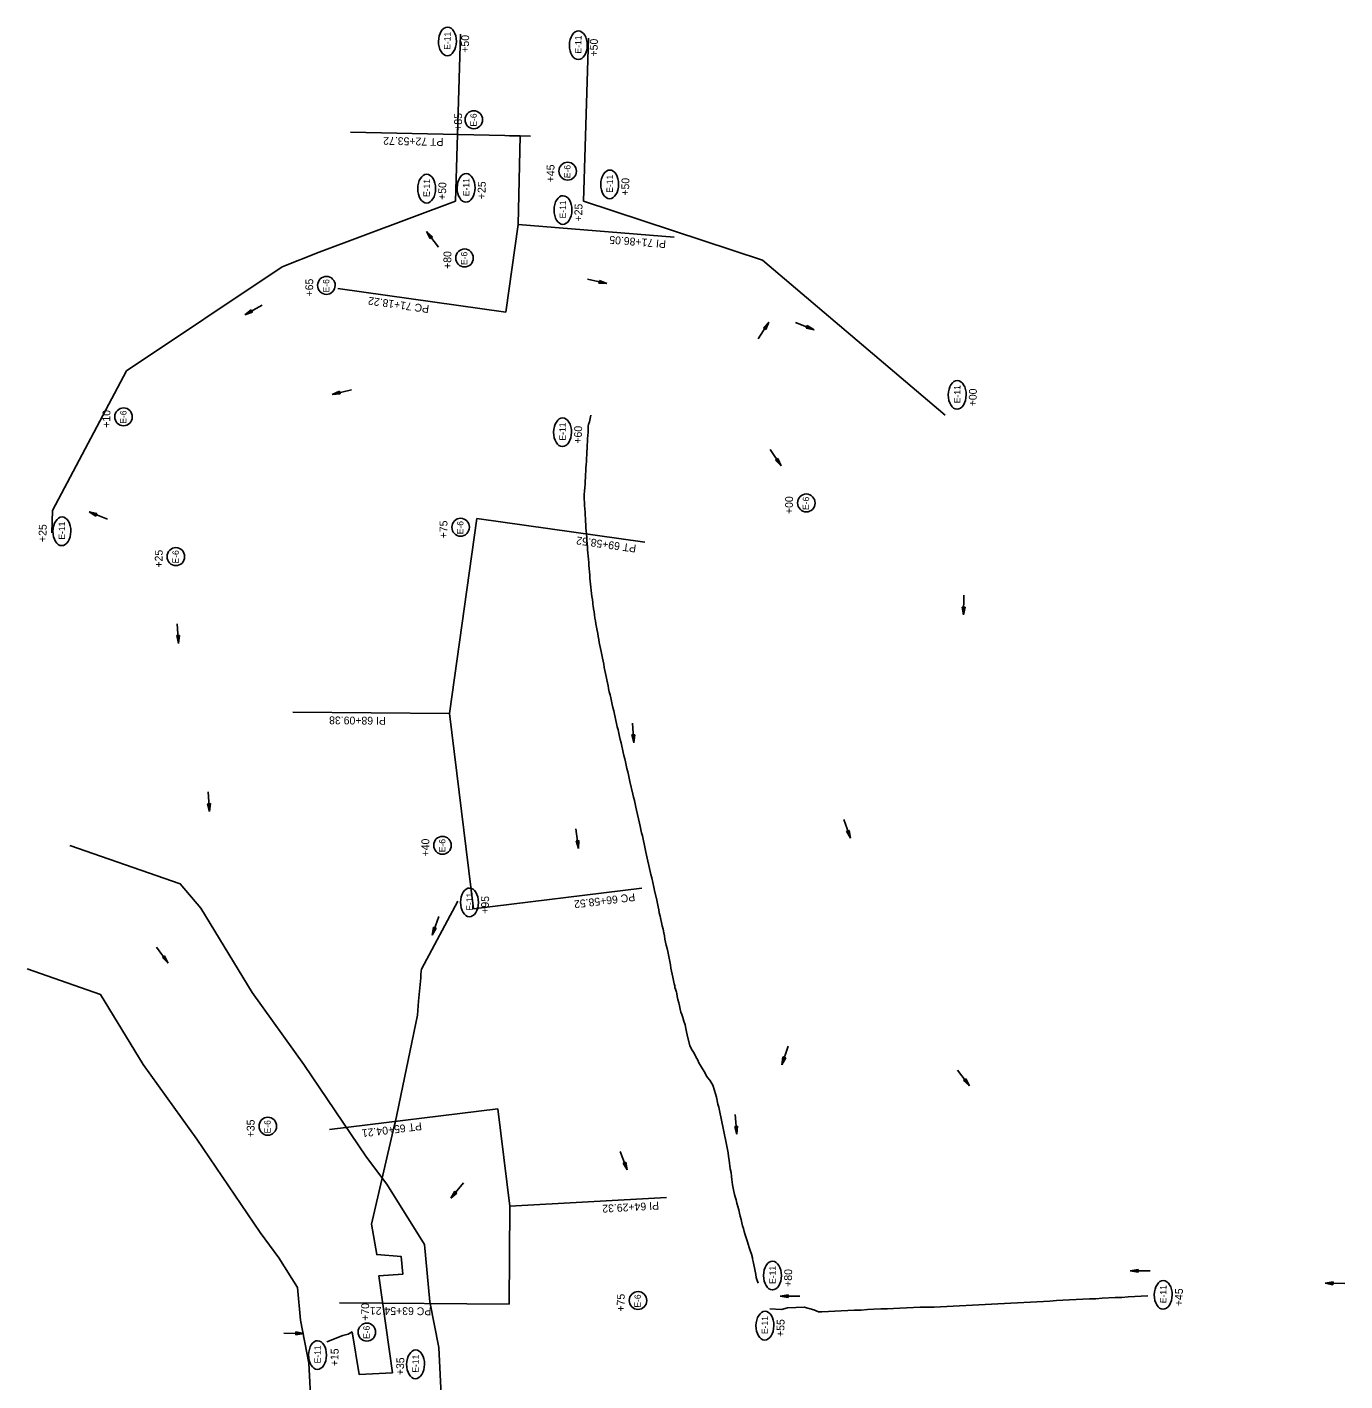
# Model space of a CAD drawing. Extents: x 1312891 to 1314734, y 2088044 to 2090982.
# Drawn here: x 1313631 to 1314640, y 2089414 to 2090451 of the extents above; entities that cross this region are included whole.
import ezdxf

# ---------------------------------------------------------------- set-up
doc = ezdxf.new("R2010")
doc.units = 0
for name, color, linetype in [('43', 7, 'Continuous'), ('44', 7, 'Continuous'), ('Level 1', 7, 'Continuous'), ('Level 44', 7, 'Continuous'), ('R_Buffer', 7, 'Continuous'), ('R_Horz Alg Annot_Detour', 7, 'Continuous'), ('R_Horz Alg Stationing_Detour', 7, 'Continuous')]:
    doc.layers.add(name, color=color, linetype=linetype)

msp = doc.modelspace()

# ---------------------------------------------------------------- linework, layer by layer
at = {"layer": '43'}
for p, q in [((1313936.8, 2090294.8), (1313941.3, 2090290.6)), ((1313939.6, 2090289.3), (1313936.8, 2090294.8)), ((1313941.3, 2090290.6), (1313939.6, 2090289.3)), ((1314068.9, 2090255.1), (1314069.3, 2090257.2)), ((1314075, 2090254.9), (1314068.9, 2090255.1)), ((1314069.3, 2090257.2), (1314075, 2090254.9)), ((1313797.7, 2090230.9), (1313802.5, 2090234.7)), ((1313803.5, 2090232.9), (1313797.7, 2090230.9)), ((1313802.5, 2090234.7), (1313803.5, 2090232.9)), ((1314194.8, 2090220.8), (1314199, 2090225.3)), ((1314199, 2090225.3), (1314196.6, 2090219.6)), ((1314227.6, 2090220.7), (1314228.4, 2090222.7)), ((1314228.4, 2090222.7), (1314233.6, 2090219.4)), ((1314196.6, 2090219.6), (1314194.8, 2090220.8)), ((1314233.6, 2090219.4), (1314227.6, 2090220.7)), ((1313864.5, 2090169.9), (1313870.1, 2090172.4)), ((1313870.1, 2090172.4), (1313870.6, 2090170.3)), ((1313870.6, 2090170.3), (1313864.5, 2090169.9)), ((1314204.1, 2090119.6), (1314205.9, 2090120.8)), ((1314208.4, 2090115.1), (1314204.1, 2090119.6)), ((1314205.9, 2090120.8), (1314208.4, 2090115.1)), ((1313678.3, 2090080), (1313684.3, 2090078.7)), ((1313683.5, 2090076.7), (1313678.3, 2090080)), ((1313684.3, 2090078.7), (1313683.5, 2090076.7)), ((1314348.2, 2090000.9), (1314347.2, 2090007)), ((1314347.2, 2090007), (1314349.4, 2090006.9)), ((1314349.4, 2090006.9), (1314348.2, 2090000.9)), ((1313745.4, 2089985.1), (1313747.5, 2089985.2)), ((1313746.9, 2089979.1), (1313745.4, 2089985.1)), ((1313747.5, 2089985.2), (1313746.9, 2089979.1)), ((1314094.1, 2089909), (1314096.3, 2089909.1)), ((1314095.6, 2089903), (1314094.1, 2089909)), ((1314096.3, 2089909.1), (1314095.6, 2089903)), ((1313769, 2089856.3), (1313771.2, 2089856.4)), ((1313770.5, 2089850.3), (1313769, 2089856.3)), ((1313771.2, 2089856.4), (1313770.5, 2089850.3)), ((1314258.5, 2089835.2), (1314260.5, 2089835.9)), ((1314261.5, 2089829.9), (1314258.5, 2089835.2)), ((1314260.5, 2089835.9), (1314261.5, 2089829.9)), ((1314051.4, 2089827.8), (1314053.5, 2089828.1)), ((1314053.3, 2089821.9), (1314051.4, 2089827.8)), ((1314053.5, 2089828.1), (1314053.3, 2089821.9)), ((1313941, 2089755.6), (1313942.1, 2089761.7)), ((1313944.1, 2089760.9), (1313941, 2089755.6)), ((1313942.1, 2089761.7), (1313944.1, 2089760.9)), ((1313734.5, 2089738.5), (1313736.2, 2089739.7)), ((1313738.9, 2089734.2), (1313734.5, 2089738.5)), ((1313736.2, 2089739.7), (1313738.9, 2089734.2)), ((1314208.9, 2089656.2), (1314209.8, 2089662.3)), ((1314209.8, 2089662.3), (1314211.9, 2089661.6)), ((1314211.9, 2089661.6), (1314208.9, 2089656.2)), ((1314348.2, 2089644.2), (1314349.8, 2089645.6)), ((1314352.7, 2089640.1), (1314348.2, 2089644.2)), ((1314349.8, 2089645.6), (1314352.7, 2089640.1)), ((1314172.9, 2089609), (1314175, 2089609.2)), ((1314174.4, 2089603.1), (1314172.9, 2089609)), ((1314175, 2089609.2), (1314174.4, 2089603.1)), ((1314087.4, 2089581), (1314089.4, 2089581.7)), ((1314090.6, 2089575.7), (1314087.4, 2089581)), ((1314089.4, 2089581.7), (1314090.6, 2089575.7)), ((1313955.4, 2089554), (1313958.4, 2089559.4)), ((1313958.4, 2089559.4), (1313960.1, 2089558)), ((1313960.1, 2089558), (1313955.4, 2089554)), ((1314475.8, 2089498.4), (1314481.9, 2089499.5)), ((1314481.9, 2089497.3), (1314475.8, 2089498.4)), ((1314481.9, 2089499.5), (1314481.9, 2089497.3)), ((1314625.1, 2089488.9), (1314631.2, 2089489.9)), ((1314631.1, 2089487.8), (1314625.1, 2089488.9)), ((1314631.2, 2089489.9), (1314631.1, 2089487.8)), ((1314207.6, 2089479.1), (1314213.7, 2089480.1)), ((1314213.7, 2089478), (1314207.6, 2089479.1)), ((1314213.7, 2089480.1), (1314213.7, 2089478)), ((1313836.6, 2089449.4), (1313836.7, 2089451.6)), ((1313842.7, 2089450.5), (1313836.6, 2089449.4)), ((1313836.7, 2089451.6), (1313842.7, 2089450.5))]:
    msp.add_line(p, q, dxfattribs=at)
for points in [[(1313945.9, 2090282.7), (1313936.8, 2090294.8)], [(1314060.2, 2090258.1), (1314075, 2090254.9)], [(1313811, 2090238.2), (1313797.7, 2090230.9)], [(1314190.8, 2090212.5), (1314199, 2090225.3)], [(1314219.5, 2090225), (1314233.6, 2090219.4)], [(1313879.3, 2090173.4), (1313864.5, 2090169.9)], [(1314199.9, 2090127.7), (1314208.4, 2090115.1)], [(1313692.4, 2090074.3), (1313678.3, 2090080)], [(1314348.4, 2090016.1), (1314348.2, 2090000.9)], [(1313745.8, 2089994.2), (1313746.9, 2089979.1)], [(1314094.6, 2089918.1), (1314095.6, 2089903)], [(1313769.5, 2089865.4), (1313770.5, 2089850.3)], [(1314256.4, 2089844.2), (1314261.5, 2089829.9)], [(1314051.1, 2089837), (1314053.3, 2089821.9)], [(1313946.2, 2089769.9), (1313941, 2089755.6)], [(1313730, 2089746.5), (1313738.9, 2089734.2)], [(1314213.8, 2089670.6), (1314208.9, 2089656.2)], [(1314343.4, 2089652.1), (1314352.7, 2089640.1)], [(1314173.3, 2089618.2), (1314174.4, 2089603.1)], [(1314085.1, 2089589.9), (1314090.6, 2089575.7)], [(1313965, 2089565.8), (1313955.4, 2089554)], [(1314491, 2089498.3), (1314475.8, 2089498.4)], [(1314640.3, 2089488.8), (1314625.1, 2089488.9)], [(1314222.8, 2089479), (1314207.6, 2089479.1)], [(1313827.5, 2089450.6), (1313842.7, 2089450.5)]]:
    msp.add_lwpolyline(points, dxfattribs=at)
at = {"layer": 'Level 1'}
for centre, major_axis, ratio in [((1313952.8, 2090440.3), (0.1, 11), 0.622952), ((1314053.1, 2090437.4), (0.1, 11), 0.622952), ((1313973, 2090380.3), (-0.05, -6.88), 0.97521), ((1314044.9, 2090340.9), (-0.05, -6.88), 0.97521), ((1313936.9, 2090327.5), (0.1, 11), 0.622952), ((1313967.1, 2090328.1), (0.1, 11), 0.622952), ((1314077.1, 2090330.8), (0.1, 11), 0.622952), ((1314041.3, 2090311.1), (0.1, 11), 0.622952), ((1313965.9, 2090274.4), (-0.05, -6.88), 0.97521), ((1313860.1, 2090253.4), (-0.05, -6.88), 0.97521), ((1314343.3, 2090169.5), (0.1, 11), 0.622952), ((1313704.7, 2090152.7), (-0.05, -6.88), 0.97521), ((1314041, 2090140.9), (0.1, 11), 0.622952), ((1314227.7, 2090086.7), (-0.05, -6.88), 0.97521), ((1313657.5, 2090065), (0.1, 11), 0.622952), ((1313962.9, 2090068.1), (-0.05, -6.88), 0.97521), ((1313744.8, 2090045.6), (-0.05, -6.88), 0.97521), ((1313949, 2089824.4), (-0.05, -6.88), 0.97521), ((1313969.7, 2089780.7), (0.1, 11), 0.622952), ((1313815.2, 2089609.2), (-0.05, -6.88), 0.97521), ((1314201.8, 2089494.8), (0.1, 11), 0.622952), ((1314501.1, 2089480), (0.1, 11), 0.622952), ((1314098.8, 2089475.7), (-0.05, -6.88), 0.97521), ((1314196, 2089456.4), (0.1, 11), 0.622952), ((1313891.1, 2089451.5), (-0.05, -6.88), 0.97521), ((1313853.3, 2089433.9), (0.1, 11), 0.622952), ((1313928.4, 2089426.8), (0.1, 11), 0.622952)]:
    msp.add_ellipse(centre, major_axis=major_axis, ratio=ratio, dxfattribs=at)
at = {"layer": 'Level 44'}
for p, q in [((1313958.9, 2090317.8), (1313854.6, 2090278.8)), ((1313958.9, 2090317.8), (1313958.9, 2090317.8)), ((1313826.3, 2090267.6), (1313706.9, 2090188))]:
    msp.add_line(p, q, dxfattribs=at)
for points in [[(1313962.9, 2090445.9), (1313958.9, 2090317.8)], [(1314057, 2090318), (1314060.8, 2090442.8)], [(1314334.1, 2090153.9), (1314194.1, 2090272.7), (1314057, 2090318)], [(1313854.6, 2090278.8), (1313826.3, 2090267.6)], [(1313706.9, 2090188), (1313650.3, 2090081), (1313649.7, 2090063.9)], [(1314057.5, 2090091), (1314057.6, 2090093.1), (1314057.9, 2090095.7), (1314058.1, 2090098.5), (1314058.2, 2090101), (1314058.4, 2090103.6), (1314058.5, 2090106), (1314058.6, 2090108.5), (1314058.8, 2090111), (1314058.9, 2090113.5), (1314059.1, 2090116), (1314059.2, 2090118.5), (1314059.4, 2090121), (1314059.5, 2090123.5), (1314059.7, 2090126), (1314059.8, 2090128.6), (1314059.9, 2090131.1), (1314060, 2090133.6), (1314060.2, 2090136), (1314060.3, 2090138.5), (1314060.5, 2090141), (1314060.6, 2090143.6), (1314060.7, 2090145.8), (1314060.8, 2090146.8), (1314061.6, 2090148.8), (1314062.6, 2090153.9)], [(1314062.6, 2090153.9), (1314062.6, 2090153.9)], [(1314138.4, 2089670.8), (1314136.5, 2089679.2), (1314135.9, 2089681.6), (1314135.4, 2089684.1), (1314134.8, 2089686.9), (1314133.9, 2089689.8), (1314133, 2089692.4), (1314132.3, 2089694.7), (1314131.7, 2089696.7), (1314131.2, 2089698.9), (1314130.6, 2089701.4), (1314130, 2089703.8), (1314129.4, 2089706.2), (1314128.9, 2089708.5), (1314128.5, 2089710.9), (1314128.3, 2089711.8), (1314127.4, 2089714.1), (1314127.1, 2089715.5), (1314126.9, 2089716.7), (1314126.6, 2089718.3), (1314126, 2089720.8), (1314125.5, 2089723.3), (1314125, 2089725.7), (1314124.5, 2089728.1), (1314124, 2089730.4), (1314123.6, 2089732.8), (1314123.1, 2089735.3), (1314122.7, 2089737.9), (1314122.1, 2089740.6), (1314121.5, 2089743), (1314121, 2089745.5), (1314120.4, 2089748), (1314119.9, 2089750.3), (1314119.4, 2089752.6), (1314119, 2089755), (1314118.5, 2089757.5), (1314118, 2089760.2), (1314117.4, 2089762.8), (1314116.8, 2089765.3), (1314116.3, 2089767.7), (1314115.7, 2089770.2), (1314115.1, 2089772.6), (1314114.7, 2089774.9), (1314114.2, 2089777.2), (1314113.7, 2089779.8), (1314113.1, 2089782.4), (1314111.4, 2089789.9), (1314110.9, 2089792.3), (1314109.3, 2089799.6), (1314108.7, 2089802.1), (1314104.8, 2089819.3), (1314104.2, 2089821.8), (1314102.1, 2089831.6), (1314101.5, 2089834.1), (1314100.4, 2089839), (1314099.8, 2089841.4), (1314097.7, 2089851.3), (1314097.1, 2089853.7), (1314096.6, 2089856.2), (1314096, 2089858.7), (1314095.4, 2089861.2), (1314094.8, 2089863.6), (1314092.6, 2089873.4), (1314092, 2089875.9), (1314091.5, 2089878.4), (1314090.9, 2089880.8), (1314090.3, 2089883.3), (1314089.7, 2089885.8), (1314089.2, 2089888.3), (1314088.6, 2089890.7), (1314088, 2089893.2), (1314087.4, 2089895.6), (1314086.9, 2089898), (1314086.3, 2089900.4), (1314085.8, 2089902.9), (1314085.2, 2089905.4), (1314084.6, 2089907.9), (1314084.1, 2089910.3), (1314083.5, 2089912.8), (1314082.9, 2089915.2), (1314082.4, 2089917.7), (1314081.8, 2089920.1), (1314081.3, 2089922.5), (1314080.7, 2089925), (1314080.2, 2089927.5), (1314079.6, 2089930), (1314079, 2089932.4), (1314078.5, 2089934.9), (1314077.9, 2089937.3), (1314077.4, 2089939.7), (1314076.8, 2089942.1), (1314076.3, 2089944.5), (1314075.8, 2089946.7), (1314075.3, 2089949), (1314074.8, 2089951.3), (1314074.3, 2089953.7), (1314073.9, 2089956), (1314073.4, 2089958.4), (1314072.9, 2089960.7), (1314072.5, 2089963.1), (1314072, 2089965.4), (1314071.6, 2089967.9), (1314071.1, 2089970.4), (1314070.5, 2089972.9), (1314070, 2089975.2), (1314069.5, 2089977.5), (1314069.1, 2089979.7), (1314068.7, 2089982), (1314068.3, 2089984.3), (1314067.9, 2089986.7), (1314067.5, 2089989.1), (1314067.1, 2089991.5), (1314066.6, 2089994), (1314066.2, 2089996.3), (1314065.8, 2089998.5), (1314065.5, 2090000.9), (1314065.1, 2090003.3), (1314064.8, 2090005.7), (1314064.4, 2090008), (1314064.3, 2090008.9), (1314064.1, 2090010.3), (1314063.8, 2090012.7), (1314063.5, 2090015.1), (1314063.2, 2090017.4), (1314062.9, 2090019.7), (1314062.7, 2090022.1), (1314062.5, 2090024.4), (1314062.2, 2090026.8), (1314062, 2090029.2), (1314061.8, 2090031.6), (1314061.6, 2090034), (1314061.4, 2090036.4), (1314061.2, 2090038.8), (1314061, 2090041.2), (1314060.8, 2090043.6), (1314060.6, 2090046), (1314060.4, 2090048.4), (1314060.2, 2090050.8), (1314060, 2090053.2), (1314059.8, 2090055.6), (1314059.6, 2090058), (1314059.5, 2090060.5), (1314059.3, 2090062.9), (1314059.1, 2090065.3), (1314058.9, 2090067.7), (1314058.8, 2090070.1), (1314058.6, 2090072.5), (1314058.5, 2090074.9), (1314058.3, 2090077.3), (1314058.2, 2090079.7), (1314058, 2090082.2), (1314057.9, 2090084.7), (1314057.7, 2090087.1), (1314057.6, 2090089.6), (1314057.5, 2090092.1)], [(1313929.9, 2089694.2), (1313930.7, 2089705.1), (1313931, 2089707.7), (1313931.2, 2089710.2), (1313931.4, 2089712.8), (1313931.6, 2089715.3), (1313931.8, 2089717.9), (1313932.1, 2089720.4), (1313932.3, 2089723), (1313932.5, 2089725.5), (1313932.8, 2089728.1), (1313932.9, 2089729.5), (1313960.7, 2089781.7)], [(1313894.7, 2089534.3), (1313912.1, 2089609.3), (1313912.7, 2089611.7), (1313929.9, 2089694.2)], [(1314190.9, 2089489.1), (1314189.7, 2089491.8), (1314189.4, 2089493.2), (1314189, 2089495.6), (1314188.5, 2089498.1), (1314188, 2089500.6), (1314187.5, 2089503.1), (1314187, 2089505.5), (1314186.6, 2089507.6), (1314186.4, 2089508.3), (1314185.7, 2089511.2), (1314184.8, 2089513.9), (1314184, 2089516.4), (1314183.2, 2089518.8), (1314182.5, 2089521.3), (1314181.7, 2089523.7), (1314180.9, 2089526.1), (1314180.2, 2089528.5), (1314179.5, 2089530.8), (1314178.9, 2089533), (1314178.3, 2089535.2), (1314177.7, 2089537.7), (1314177.1, 2089540.2), (1314176.5, 2089542.6), (1314175.9, 2089545.1), (1314175.3, 2089547.7), (1314174.6, 2089550.2), (1314173.9, 2089552.7), (1314173.2, 2089555.1), (1314172.7, 2089556.8), (1314172.7, 2089556.9), (1314172.2, 2089559.3), (1314171.7, 2089561.8), (1314171.2, 2089564.3), (1314170.9, 2089566.3), (1314170.6, 2089568.3), (1314170.4, 2089570.8), (1314170.1, 2089573.7), (1314169.5, 2089576.6), (1314169.1, 2089578.8), (1314168.8, 2089580.8), (1314168.5, 2089583.3), (1314168.2, 2089585.9), (1314167.8, 2089588.8), (1314167.3, 2089591.5), (1314166.8, 2089594), (1314166.3, 2089596.5), (1314165.8, 2089599), (1314165.3, 2089601.4), (1314164.8, 2089603.9), (1314164.3, 2089606.4), (1314163.7, 2089608.9), (1314163.2, 2089611.4), (1314162.7, 2089613.8), (1314162.2, 2089616.3), (1314161.6, 2089618.7), (1314161.1, 2089621.2), (1314160.6, 2089623.7), (1314160, 2089626.2), (1314159.5, 2089628.6), (1314159.1, 2089630.4), (1314159, 2089631), (1314158.8, 2089631.6), (1314158.1, 2089634.1), (1314157.4, 2089636.7), (1314156.2, 2089640.6), (1314153.7, 2089644.4), (1314152, 2089646.6), (1314151.1, 2089648.1), (1314150, 2089650.4), (1314148.3, 2089653.3), (1314146.7, 2089655.8), (1314145.5, 2089657.7), (1314144.5, 2089659.7), (1314143.2, 2089662.3), (1314141.7, 2089665.1), (1314140.3, 2089667.4), (1314138.4, 2089670.8)], [(1313910.8, 2089420.4), (1313900.3, 2089494.7), (1313918.7, 2089495.9), (1313917.4, 2089509.3), (1313898.7, 2089510.9), (1313894.7, 2089534.3)], [(1314489.3, 2089479.2), (1314474.3, 2089478.4), (1314469.3, 2089478.1), (1314464.3, 2089477.9), (1314454.3, 2089477.4), (1314449.4, 2089477.1), (1314444.5, 2089476.9), (1314439.5, 2089476.7), (1314434.4, 2089476.5), (1314429.3, 2089476.2), (1314424.3, 2089475.9), (1314419.3, 2089475.6), (1314414.3, 2089475.3), (1314409.3, 2089475), (1314404.4, 2089474.7), (1314399.4, 2089474.4), (1314394.4, 2089474.2), (1314389.4, 2089473.9), (1314384.4, 2089473.7), (1314379.5, 2089473.4), (1314374.5, 2089473.2), (1314369.5, 2089472.9), (1314325.7, 2089470.7)], [(1314208.8, 2089468.8), (1314199.7, 2089469.2)], [(1314325.7, 2089470.7), (1314314.8, 2089470.5), (1314309.7, 2089470.3), (1314304.5, 2089470.1), (1314299.4, 2089469.8), (1314294.6, 2089469.5), (1314289.8, 2089469.4), (1314284.7, 2089469.2), (1314279.5, 2089469), (1314274.5, 2089468.7), (1314269.6, 2089468.4), (1314264.7, 2089468.2), (1314259.6, 2089468), (1314254.5, 2089467.7), (1314249.5, 2089467.4), (1314244.6, 2089467.2), (1314239.7, 2089467), (1314237.1, 2089466.9), (1314233.4, 2089468.6), (1314226.1, 2089470.5), (1314219.6, 2089470.3), (1314213.3, 2089470.2), (1314208.8, 2089468.8)], [(1313860.3, 2089444), (1313872.6, 2089448.9), (1313876.7, 2089449.8), (1313879.9, 2089451.7)], [(1313879.9, 2089451.7), (1313885.2, 2089419), (1313910.8, 2089420.4)]]:
    msp.add_lwpolyline(points, dxfattribs=at)
at = {"layer": 'R_Buffer'}
for points in [[(1314398.1, 2088926.4), (1314279.1, 2088981), (1314219.3, 2089047.5), (1314174.9, 2089087.2), (1314129, 2089112), (1314090.9, 2089118.4), (1313947.3, 2089119.9), (1313951.5, 2089132.9), (1313959.5, 2089171.9), (1313955.9, 2089247.9), (1313958.3, 2089279.9), (1313950.4, 2089321.3), (1313950, 2089362.1), (1313946.1, 2089439.7), (1313939.4, 2089474.8), (1313935.3, 2089518.7), (1313906.3, 2089564.9), (1313890.9, 2089585.6), (1313842.8, 2089656.5), (1313803.2, 2089711.6), (1313763.9, 2089776.4), (1313748.1, 2089794.9), (1313663.5, 2089824.2)], [(1313850.1, 2089359.2), (1313846.6, 2089427.6), (1313840.2, 2089460.7), (1313837.9, 2089485.7), (1313823.7, 2089508.4), (1313809.4, 2089527.7), (1313760.8, 2089599.3), (1313719.7, 2089656.4), (1313687.1, 2089710.2), (1313630.8, 2089729.7)]]:
    msp.add_lwpolyline(points, dxfattribs=at)
at = {"layer": 'R_Horz Alg Annot_Detour'}
for points in [[(1314008.4, 2090367.9), (1313878.5, 2090370.7)], [(1313997.6, 2090232.9), (1314007, 2090300.1), (1314008.4, 2090367.9)], [(1314007, 2090300.1), (1314126.6, 2090290.4)], [(1313997.6, 2090232.9), (1313868.8, 2090251)], [(1313972.7, 2089775.7), (1313954.3, 2089925.4), (1313975.3, 2090074.8)], [(1313975.3, 2090074.8), (1314104.1, 2090056.7)], [(1313954.3, 2089925.4), (1313834.3, 2089926.4)], [(1313972.7, 2089775.7), (1314101.8, 2089791.5)], [(1313991.5, 2089622.5), (1313862.5, 2089606.6)], [(1314000, 2089472.8), (1314000.7, 2089547.9), (1313991.5, 2089622.5)], [(1314000.7, 2089547.9), (1314120.5, 2089554.7)], [(1314000, 2089472.8), (1313870, 2089474)]]:
    msp.add_lwpolyline(points, dxfattribs=at)
at = {"layer": 'R_Horz Alg Stationing_Detour'}
msp.add_lwpolyline([(1314000.4, 2090368.1), (1314016.4, 2090367.7)], dxfattribs=at)

# ---------------------------------------------------------------- texts
at = {"layer": '44'}
for s, rotation, p in [('+50', 88.324, (1313969.1, 2090431.6)), ('+50', 88.324, (1314067.7, 2090428.7)), ('+85', 89.5, (1313963.9, 2090371.8)), ('+45', 89.5, (1314034.7, 2090332.4)), ('+50', 88.324, (1313951.6, 2090318.8)), ('+25', 88.324, (1313981.8, 2090319.4)), ('+50', 88.324, (1314091.8, 2090322.1)), ('+25', 88.324, (1314055.9, 2090302.3)), ('+80', 89.5, (1313955.7, 2090266)), ('+65', 89.5, (1313849.9, 2090244.9)), ('+00', 88.324, (1314358, 2090160.7)), ('+10', 89.5, (1313694.5, 2090144.3)), ('+60', 88.324, (1314055.6, 2090132.1)), ('+00', 89.5, (1314217.4, 2090078.2)), ('+25', 88.324, (1313645.5, 2090056.7)), ('+75', 89.5, (1313952.7, 2090059.6)), ('+25', 89.5, (1313734.6, 2090037.2)), ('+40', 89.5, (1313938.8, 2089815.9)), ('+95', 88.324, (1313984.4, 2089771.9)), ('+35', 89.5, (1313805, 2089600.7)), ('+80', 88.324, (1314216.5, 2089486.1)), ('+75', 89.5, (1314088.5, 2089467.2)), ('+45', 88.324, (1314515.8, 2089471.3)), ('+70', 89.5, (1313892.7, 2089460.1)), ('+55', 88.324, (1314210.7, 2089447.7)), ('+15', 88.324, (1313869.1, 2089425.3)), ('+35', 88.324, (1313919.4, 2089418.4))]:
    msp.add_text(s, height=6, rotation=rotation, dxfattribs=at).set_placement(p)
at = {"layer": 'Level 1'}
for s, rotation, p in [('E-11 ', 89.5, (1313955.1, 2090433.9)), ('E-11 ', 89.5, (1314055.4, 2090431)), ('E-6 ', 89.558, (1313975.2, 2090375)), ('E-6 ', 89.558, (1314047, 2090335.5)), ('E-11 ', 89.5, (1314079.5, 2090324.4)), ('E-11 ', 89.5, (1313939.3, 2090321.1)), ('E-11 ', 89.5, (1313969.5, 2090321.7)), ('E-11 ', 89.5, (1314043.6, 2090304.7)), ('E-6 ', 89.558, (1313968, 2090269)), ('E-6 ', 89.558, (1313862.3, 2090248)), ('E-11 ', 89.5, (1314345.7, 2090163.1)), ('E-6 ', 89.558, (1313706.9, 2090147.4)), ('E-11 ', 89.5, (1314043.3, 2090134.5)), ('E-6 ', 89.558, (1314229.8, 2090081.3)), ('E-11 ', 89.5, (1313659.8, 2090058.6)), ('E-6 ', 89.558, (1313965, 2090062.7)), ('E-6 ', 89.558, (1313747, 2090040.3)), ('E-6 ', 89.558, (1313951.2, 2089819.1)), ('E-11 ', 89.5, (1313972.1, 2089774.3)), ('E-6 ', 89.558, (1313817.3, 2089603.7)), ('E-11 ', 89.5, (1314204.2, 2089488.4)), ('E-11 ', 89.5, (1314503.5, 2089473.6)), ('E-6 ', 89.558, (1314100.9, 2089470.2)), ('E-6 ', 89.558, (1313893.2, 2089446.2)), ('E-11 ', 89.5, (1314198.3, 2089450)), ('E-11 ', 89.5, (1313855.6, 2089427.5)), ('E-11 ', 89.5, (1313930.7, 2089420.4))]:
    msp.add_text(s, height=4.88, rotation=rotation, dxfattribs=at).set_placement(p)
at = {"layer": 'R_Horz Alg Annot_Detour'}
for s, rotation, p in [('PT 72+53.72', 178.775, (1313949.8, 2090366.2)), ('PI 71+86.05', 175.3875, (1314120.4, 2090287.9)), ('PC 71+18.22', 172, (1313939.1, 2090238.1)), ('PT 69+58.52', 172, (1314097.7, 2090054.6)), ('PI 68+09.38', 179.5, (1313905.7, 2089922.8)), ('PC 66+58.52', 187, (1314096.2, 2089787.8)), ('PT 65+04.21', 187, (1313932.8, 2089612.3)), ('PI 64+29.32', 183.25, (1314114.7, 2089551.4)), ('PC 63+54.21', 179.5, (1313940.5, 2089470.4))]:
    msp.add_text(s, height=6, rotation=rotation, dxfattribs=at).set_placement(p)

doc.saveas('drawing.dxf')
